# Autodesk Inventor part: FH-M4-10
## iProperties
FINISH: PASSIVATE
d3: 2.500 mm
head_diameter: 9.600 mm
Author: Ron Crain
Revision Number: 1
Shininess: 64.0
Angle Display Precision: 2
Document Length Units: 11269
Document Angle Units: 11284
Document Time Units: 11279
Document Mass Units: 11290
Document Length Units Precision: 3
Document Angle Units Precision: 2
Compacted: True
PropertySet Name: _Private Model Information
Created: 2002-07
Part Number: FH-M4-10
Material: Steel, High Strength Low Alloy
Description: STUD, SELF CLINCH,  M4x0.7 X 10
Vendor: PENN ENG & MFG
Document SubType Name: Modeling
Designer: Ron Crain
Control State: 0
Master: False
Checked Out: False
PropertySet Name: Design Tracking Control
Density: 0.0
Volumn: 0.0
Area: 0.0
PropertySet Name: Model Information
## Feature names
1. Shank [Extrusion]
2. Head [Extrusion]
3. Chamfer1
